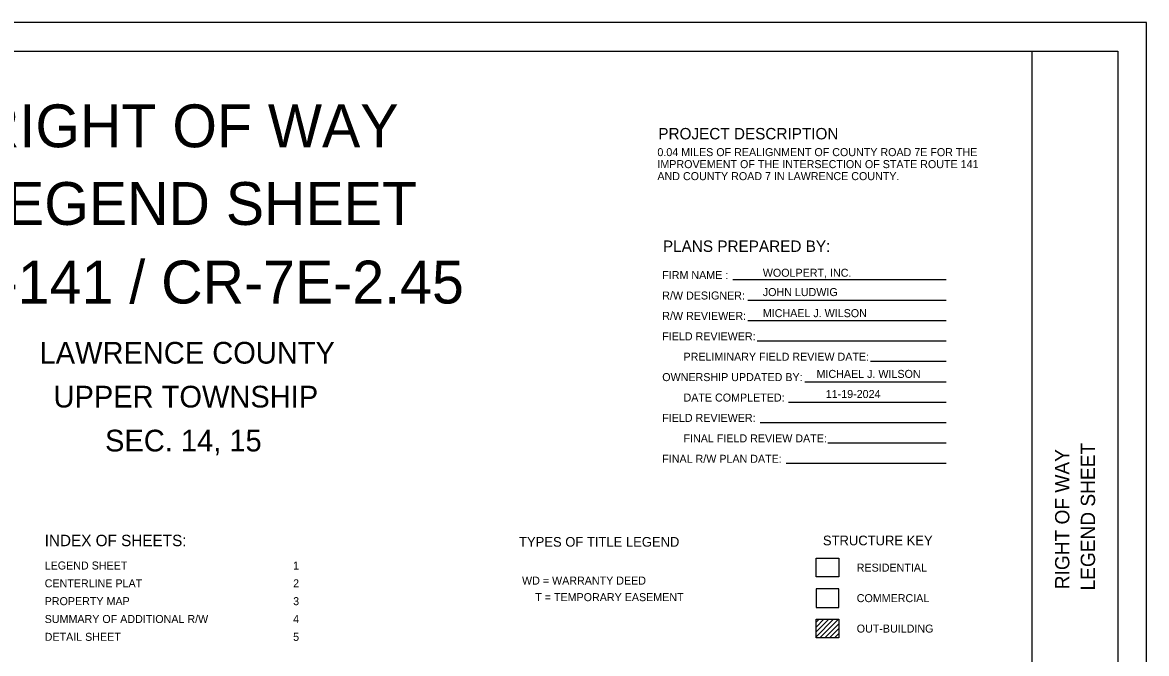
# Model space of a CAD drawing. Extents: x 0 to 34, y 0 to 22.
# Drawn here: x 14.34 to 34, y 10.96 to 22 of the extents above; entities that cross this region are included whole.
import ezdxf

# ---------------------------------------------------------------- set-up
doc = ezdxf.new("R2010")
doc.units = 0
for name, color, linetype in [('SC_Shading1', 7, 'Continuous'), ('SH_Border', 7, 'Continuous'), ('SH_Cut_Line', 7, 'Continuous'), ('SH_Data', 7, 'Continuous'), ('SH_Text', 7, 'Continuous')]:
    doc.layers.add(name, color=color, linetype=linetype)

msp = doc.modelspace()

# ---------------------------------------------------------------- linework, layer by layer
at = {"layer": 'SC_Shading1'}
msp.add_lwpolyline([(28.222, 11.765), (28.619, 11.765), (28.619, 12.091), (28.222, 12.091)], close=True, dxfattribs=at)
at = {"layer": 'SH_Border'}
msp.add_line((32, 0.5), (32, 21.5), dxfattribs=at)
msp.add_lwpolyline([(1.5, 21.5), (33.5, 21.5), (33.5, 0.5), (1.5, 0.5)], close=True, dxfattribs=at)
at = {"layer": 'SH_Cut_Line'}
msp.add_lwpolyline([(0, 0), (34, 0), (34, 22), (0, 22)], close=True, dxfattribs=at)
at = {"layer": 'SH_Text'}
for p, q in [((26.761, 17.5), (30.498, 17.5)), ((27.025, 17.142), (30.498, 17.142)), ((27.025, 16.785), (30.498, 16.785)), ((27.189, 16.428), (30.498, 16.428)), ((29.17, 16.071), (30.498, 16.071)), ((28.025, 15.714), (30.498, 15.714)), ((27.74, 15.356), (30.498, 15.356)), ((27.243, 15), (30.498, 15)), ((28.423, 14.642), (30.498, 14.642)), ((27.695, 14.286), (30.498, 14.286)), ((28.222, 11.555), (28.223, 11.556)), ((28.222, 11.505), (28.273, 11.556)), ((28.222, 11.42), (28.358, 11.556)), ((28.222, 11.335), (28.442, 11.556)), ((28.222, 11.25), (28.527, 11.556)), ((28.286, 11.23), (28.612, 11.556)), ((28.371, 11.23), (28.619, 11.478)), ((28.222, 11.235), (28.226, 11.23)), ((28.455, 11.23), (28.619, 11.393)), ((28.54, 11.23), (28.619, 11.309))]:
    msp.add_line(p, q, dxfattribs=at)
for points in [[(28.222, 12.627), (28.619, 12.627), (28.619, 12.301), (28.222, 12.301)], [(28.222, 11.556), (28.619, 11.556), (28.619, 11.23), (28.222, 11.23)]]:
    msp.add_lwpolyline(points, close=True, dxfattribs=at)

# ---------------------------------------------------------------- texts
at = {"layer": 'SH_Data'}
for s, height, p in [('RIGHT OF WAY', 0.75, (13.561, 19.816)), ('LEGEND SHEET', 0.75, (13.492, 18.457)), ('LAW-141 / CR-7E-2.45', 0.75, (11.747, 17.082)), ('WOOLPERT, INC.', 0.14, (27.288, 17.55)), ('JOHN LUDWIG', 0.14, (27.288, 17.212)), ('MICHAEL J. WILSON', 0.14, (27.288, 16.843)), ('LAWRENCE COUNTY', 0.38, (14.636, 16.03)), ('MICHAEL J. WILSON', 0.14, (28.228, 15.78)), ('UPPER TOWNSHIP', 0.38, (14.88, 15.262)), ('11-19-2024', 0.14, (28.389, 15.428)), ('SEC. 14, 15', 0.38, (15.782, 14.493)), ('INDEX OF SHEETS:', 0.2, (14.726, 12.835)), ('LEGEND SHEET', 0.14, (14.726, 12.427)), ('1', 0.14, (19.072, 12.427)), ('CENTERLINE PLAT', 0.14, (14.726, 12.115)), ('2', 0.14, (19.072, 12.115)), ('PROPERTY MAP', 0.14, (14.726, 11.803)), ('3', 0.14, (19.072, 11.803)), ('SUMMARY OF ADDITIONAL R/W', 0.14, (14.726, 11.491)), ('4', 0.14, (19.072, 11.491)), ('DETAIL SHEET', 0.14, (14.726, 11.179)), ('5', 0.14, (19.072, 11.179))]:
    msp.add_text(s, height=height, dxfattribs=at).set_placement(p)
for s, p in [('LEGEND SHEET', (33.1, 12.06)), ('RIGHT OF WAY', (32.65, 12.082))]:
    msp.add_text(s, height=0.25, rotation=90, dxfattribs=at).set_placement(p)
at = {"layer": 'SH_Text'}
for s, height, p in [('PROJECT DESCRIPTION', 0.2, (25.46, 19.954)), ('0.04 MILES OF REALIGNMENT OF COUNTY ROAD 7E FOR THE ', 0.14, (25.444, 19.661)), ('IMPROVEMENT OF THE INTERSECTION OF STATE ROUTE 141 ', 0.14, (25.444, 19.451)), ('AND COUNTY ROAD 7 IN LAWRENCE COUNTY.', 0.14, (25.444, 19.241)), ('PLANS PREPARED BY:', 0.2, (25.541, 17.985)), ('FIRM NAME :', 0.14, (25.529, 17.51)), ('R/W DESIGNER:', 0.14, (25.529, 17.152)), ('R/W REVIEWER:', 0.14, (25.529, 16.795)), ('FIELD REVIEWER:', 0.14, (25.529, 16.438)), ('PRELIMINARY FIELD REVIEW DATE:', 0.14, (25.901, 16.081)), ('OWNERSHIP UPDATED BY:', 0.14, (25.529, 15.724)), ('DATE COMPLETED:', 0.14, (25.901, 15.366)), ('FIELD REVIEWER:', 0.14, (25.529, 15.01)), ('FINAL FIELD REVIEW DATE:', 0.14, (25.901, 14.652)), ('FINAL R/W PLAN DATE:', 0.14, (25.529, 14.295)), ('TYPES OF TITLE LEGEND', 0.17, (23.024, 12.826)), ('STRUCTURE KEY', 0.17, (28.339, 12.85)), ('RESIDENTIAL', 0.14, (28.931, 12.39)), ('WD = WARRANTY DEED', 0.14, (23.076, 12.163)), ('T = TEMPORARY EASEMENT', 0.14, (23.307, 11.873)), ('COMMERCIAL', 0.14, (28.931, 11.856)), ('OUT-BUILDING', 0.14, (28.931, 11.323))]:
    msp.add_text(s, height=height, dxfattribs=at).set_placement(p)

doc.saveas('drawing.dxf')
